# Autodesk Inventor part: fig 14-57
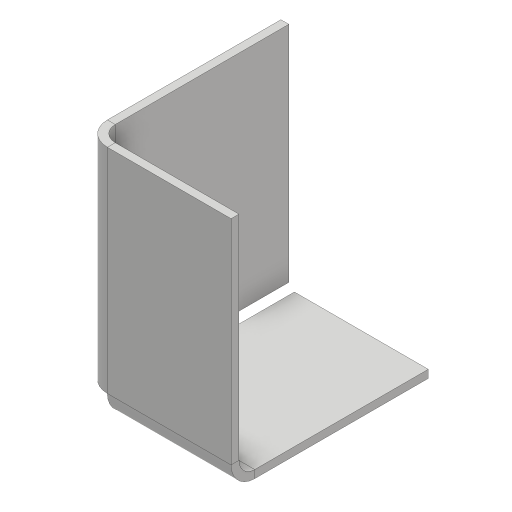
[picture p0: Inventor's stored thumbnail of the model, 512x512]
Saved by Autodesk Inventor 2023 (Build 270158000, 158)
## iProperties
Created: 2017-05
Part Number: fig 14-57
Material: Generic
Document SubType Name: Sheet Metal
Designer: CADCIM 00
Density: 1 g/cm^3
Sheet Metal Rule: Default_mm
Appearance: Default
Author: CADCIM 00
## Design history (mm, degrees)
node "Face1"
  sketch "Sketch1"
    geometry: L1 (0, 0)-(-15.678, 0); L2 (-15.678, 0)-(-15.678, -27.036); L3 (-15.678, -27.036)-(0, -27.036); L4 (0, -27.036)-(0, 0)
    constraints: 8 end point, 2 parallel, 1 horizontal, 1 perpendicular
node "Flange1"
body "Solid1"
face "Plate1" dims "d0" = 1 (= Thickness)
sketch "Sketch2"
  geometry: L1 (-22, 0)-(-22, -27.036); L2 (-22, -27.036)-(0, -27.036); 1 other entity
  constraints: 4 end point, 4 other
face "Plate2" dims "d0" = 1 (= Thickness), "d1" = 1 (= BendReliefWidth), "d2" = 0.5 (= BendReliefDepth), "d3" = 2 (= MinimumRemnant), "d4" = 2 (= TransitionRadius), "d5" = 25, "d6" = 90 deg, "d7" = 2 (= BendRadius), "d8" = 4 (= CornerReliefSize), "d9" = 1 (= GapSize), "d10" = 2 (= JacobiRadiusSize), "SeamGap" = 0.01
bend "Bend1" dims "d0" = 1 (= Thickness), "d1" = 1 (= BendReliefWidth), "d2" = 0.5 (= BendReliefDepth), "d3" = 2 (= MinimumRemnant), "d4" = 2 (= TransitionRadius), "d5" = 25, "d6" = 90 deg, "d7" = 2 (= BendRadius), "SeamGap" = 0.01
feature "Corner1" dims "d5" = 25, "d6" = 90 deg, "d8" = 4 (= CornerReliefSize), "d9" = 1 (= GapSize), "d10" = 2 (= JacobiRadiusSize)
other parameters: "Thickness" = 1 (derived), "BendRadius" = 2 (= 2 x Thickness), "BendReliefWidth" = 1 (= Thickness), "BendReliefDepth" = 0.5 (= 0.5 x Thickness), "CornerReliefSize" = 4 (= 4 x Thickness), "MinimumRemnant" = 2 (= 2 x Thickness), "TransitionRadius" = 2 (= BendRadius), "JacobiRadiusSize" = 2 (= BendRadius), "GapSize" = 1 (= Thickness)
